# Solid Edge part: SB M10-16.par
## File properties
Author: Dan
Template: metric part.par
Last saved by: Dan
Revision: 4
Application: Solid Edge
Material: Steel
Face Style: Steel
Fill Style: ANSI32(Steel)
Virtual Style: Machined steel
Coef. of Thermal Exp: 1.3e-05
Thermal Conductivity: 32.0
Specific Heat: 481.0
Modulus of Elasticity: 199947953000.0
Poisson's Ratio: 0.29
Yield Stress: 262000766.0
Ultimate Stress: 358527364.0
Elongation: 0.0
Density: 7833.000 kg/m^3
Accuracy: 0.990
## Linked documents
SBM10-16.par
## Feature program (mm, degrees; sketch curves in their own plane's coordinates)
part copy "CopiedPart_1"
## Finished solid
Body 1: solid body, 16 faces, 26 edges, 12 vertices.
  Faces by surface: plane 11, cylinder 3, cone 1, torus 1
  Edges by curve: line 18, circle 8
Bounding box of the edges (mm; curved faces can reach further): 39.000 x 18.000 x 18.000, from (-25, -9, -9) to (14, 9, 9).
Cylindrical faces by radius (mm): R5 x1, R6 x1, R9 x1
Conical faces (half-angle, radius in mm at the cone's reference point): 45 deg R5 x1
Toroidal faces (ring radius, tube radius in mm): R8 r1 x1
Planar faces by outward normal: +x 3, +z 1, -x 2, -z 1, oblique 4
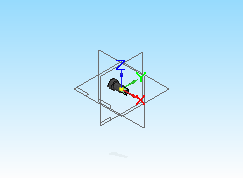
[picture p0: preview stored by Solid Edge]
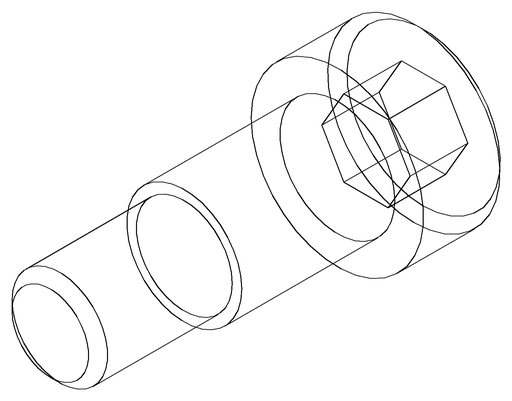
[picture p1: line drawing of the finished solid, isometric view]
